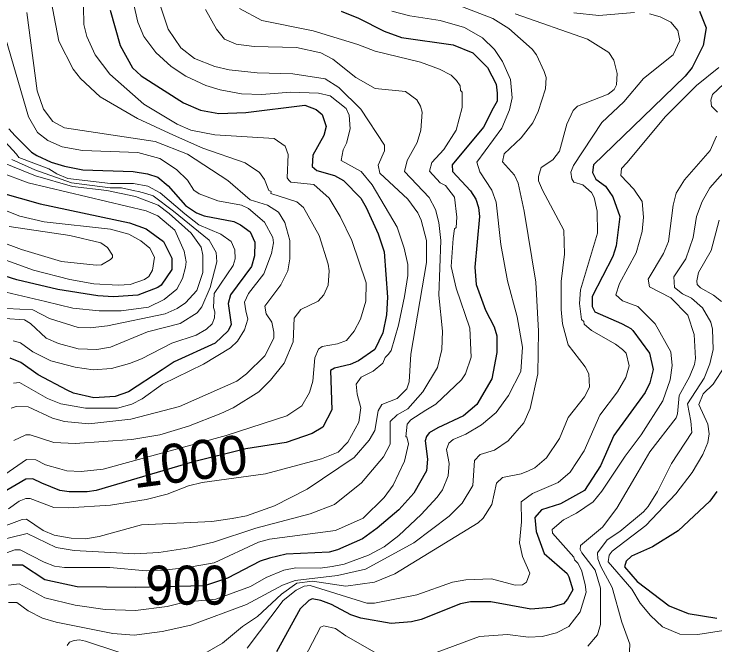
# Model space of a CAD drawing. Extents: x 423 to 448.8, y 7456.3 to 7484.
# Drawn here: x 436.1 to 437.534, y 7472.399 to 7473.69 of the extents above; entities that cross this region are included whole.
import ezdxf
from ezdxf.enums import TextEntityAlignment as Align

# ---------------------------------------------------------------- set-up
doc = ezdxf.new("R2010")
doc.units = 0
doc.header["$LTSCALE"] = 0.032
doc.layers.add('1', color=7, linetype='Continuous', lineweight=25)
doc.layers.add('2', color=7, linetype='Continuous', lineweight=13)
doc.layers.add('61', color=7, linetype='Continuous')

msp = doc.modelspace()

# ---------------------------------------------------------------- linework, layer by layer
at = {"layer": '1'}
for points in [[(436.2966, 7473.6981), (436.3167, 7473.6254), (436.3422, 7473.5797), (436.36, 7473.5635), (436.4466, 7473.5086), (436.4815, 7473.4931), (436.5186, 7473.4862), (436.5743, 7473.4885), (436.6949, 7473.5039), (436.7181, 7473.4947), (436.7305, 7473.4846), (436.7382, 7473.4599), (436.7336, 7473.4413), (436.7112, 7473.4011), (436.7096, 7473.3778), (436.7197, 7473.3701), (436.7553, 7473.3593), (436.7738, 7473.3492), (436.8094, 7473.3129), (436.8202, 7473.2944), (436.845, 7473.2402), (436.8574, 7473.2031), (436.8643, 7473.1103), (436.862, 7473.0747), (436.8543, 7473.0376), (436.838, 7473.0035), (436.8047, 7472.9803), (436.7878, 7472.9726), (436.7552, 7472.9656), (436.7475, 7472.9602), (436.7498, 7472.8798), (436.732, 7472.8442), (436.7096, 7472.8318), (436.6563, 7472.8132), (436.574, 7472.8), (436.464, 7472.7727), (436.268, 7472.715), (436.2494, 7472.7119), (436.2123, 7472.7119), (436.1937, 7472.715), (436.1566, 7472.7297), (436.138, 7472.739), (436.1241, 7472.7382), (436.0762, 7472.7103)], [(436.7692, 7473.6958), (436.8048, 7473.6818), (436.8574, 7473.6548), (436.8929, 7473.6424), (436.9981, 7473.6269), (437.0383, 7473.6107), (437.0685, 7473.5805), (437.0863, 7473.5465), (437.0886, 7473.5279), (437.0883, 7473.5116), (437.0801, 7473.4977), (437.0607, 7473.4583), (436.9965, 7473.3817), (436.9973, 7473.3678), (437.0337, 7473.3284), (437.0445, 7473.3114), (437.0499, 7473.2944), (437.0523, 7473.2758), (437.043, 7473.1721), (437.0453, 7473.1366), (437.0646, 7473.084), (437.0824, 7473.0499), (437.0878, 7473.0314), (437.0878, 7472.9973), (437.0778, 7472.9432), (437.0468, 7472.8906), (437.0198, 7472.8674), (436.9672, 7472.8434), (436.9494, 7472.8326), (436.944, 7472.8256), (436.9409, 7472.8164), (436.9455, 7472.7792), (436.944, 7472.7552), (436.9177, 7472.7096), (436.8875, 7472.6755), (436.8426, 7472.6377), (436.8125, 7472.616), (436.7615, 7472.5936), (436.7444, 7472.5889), (436.6563, 7472.5843), (436.6222, 7472.5766), (436.6037, 7472.5704), (436.5364, 7472.5356), (436.4894, 7472.5194), (436.3492, 7472.5162), (436.2293, 7472.5178), (436.1628, 7472.5317), (436.1171, 7472.5619), (436.0963, 7472.5619)], [(437.5024, 7473.6958), (437.5163, 7473.6617), (437.5102, 7473.6254), (437.4877, 7473.5805), (437.473, 7473.5627), (437.4073, 7473.4993), (437.2858, 7473.3817), (437.2835, 7473.3655), (437.2905, 7473.3523), (437.3098, 7473.3377), (437.3253, 7473.316), (437.3392, 7473.2758), (437.3322, 7473.2155), (437.3253, 7473.1938), (437.2828, 7473.1118), (437.2828, 7473.0917), (437.2881, 7473.0809), (437.3431, 7473.0569), (437.3547, 7473.0507), (437.3622, 7473.0467), (437.3663, 7473.0422), (437.4003, 7472.9958), (437.4073, 7472.9625), (437.4011, 7472.9355), (437.391, 7472.9154), (437.3268, 7472.8272), (437.2998, 7472.7653), (437.2673, 7472.715), (437.2178, 7472.6879), (437.1791, 7472.6755), (437.1652, 7472.6593), (437.1683, 7472.6307), (437.1845, 7472.5859), (437.2317, 7472.5448), (437.2348, 7472.5379), (437.2433, 7472.5116), (437.2325, 7472.4923), (437.224, 7472.483), (437.1977, 7472.4752), (437.1575, 7472.4721), (437.0755, 7472.4868), (437.0337, 7472.4868), (437.0136, 7472.483), (436.9332, 7472.4505), (436.9131, 7472.4459), (436.8713, 7472.4427), (436.8094, 7472.4536), (436.7893, 7472.4605), (436.7491, 7472.4814), (436.7274, 7472.4899), (436.7096, 7472.493), (436.7027, 7472.4899), (436.6856, 7472.4729), (436.6369, 7472.3848)], [(436.0893, 7473.4552), (436.1024, 7473.4405), (436.1357, 7473.4072), (436.1465, 7473.4003), (436.1756, 7473.3866), (436.2029, 7473.3786), (436.2403, 7473.3712), (436.3438, 7473.3678), (436.3732, 7473.3632)], [(436.3732, 7473.3632), (436.394, 7473.3562), (436.4149, 7473.3384), (436.4505, 7473.2982), (436.4729, 7473.2835), (436.4891, 7473.2773), (436.5495, 7473.2657), (436.5634, 7473.2588), (436.5828, 7473.2441), (436.5928, 7473.2232), (436.5921, 7473.1953), (436.5859, 7473.1736), (436.5426, 7473.1157), (436.5379, 7473.0979), (436.5441, 7473.0546), (436.5379, 7473.0414), (436.5116, 7473.0167), (436.4273, 7472.978), (436.4026, 7472.9617), (436.3337, 7472.9169), (436.3067, 7472.9076), (436.2633, 7472.9045), (436.2216, 7472.9138), (436.2084, 7472.92), (436.1489, 7472.9517), (436.114, 7472.9772), (436.0916, 7472.9857)], [(436.0715, 7473.3245), (436.1535, 7473.3013), (436.3361, 7473.2626), (436.3701, 7473.2502), (436.4056, 7473.2247), (436.4227, 7473.1907), (436.4227, 7473.1675), (436.401, 7473.135), (436.394, 7473.1304), (436.3531, 7473.1149), (436.3036, 7473.111), (436.2711, 7473.1133), (436.1891, 7473.1265), (436.1056, 7473.1458), (436.0073, 7473.1768)], [(437.538, 7472.7127), (437.5233, 7472.6933), (437.4591, 7472.6322), (437.4065, 7472.5998), (437.3632, 7472.5804), (437.3523, 7472.5704), (437.3492, 7472.5588), (437.3748, 7472.5286), (437.4405, 7472.4791), (437.4792, 7472.4629), (437.538, 7472.4536)]]:
    msp.add_lwpolyline(points, dxfattribs=at)
at = {"layer": '2'}
for points in [[(436.3399, 7473.7306), (436.3531, 7473.6733), (436.3654, 7473.644), (436.3902, 7473.6114), (436.4211, 7473.5828), (436.4513, 7473.5627), (436.4923, 7473.5441), (436.5217, 7473.5349), (436.565, 7473.5271), (436.6068, 7473.5256), (436.6655, 7473.5302), (436.7228, 7473.5279), (436.7467, 7473.5225), (436.7792, 7473.497), (436.7854, 7473.4831), (436.7877, 7473.4552), (436.78, 7473.4258), (436.773, 7473.4119), (436.7692, 7473.3902), (436.8101, 7473.3678), (436.8326, 7473.3408), (436.8837, 7473.2541), (436.8983, 7473.2108), (436.9053, 7473.1775), (436.9053, 7473.1551), (436.8991, 7473.1118), (436.8867, 7473.053), (436.8712, 7473.0012), (436.8658, 7472.9942), (436.8589, 7472.9873), (436.8543, 7472.9756), (436.8349, 7472.9594), (436.8102, 7472.947), (436.8001, 7472.9324), (436.8016, 7472.9123), (436.8094, 7472.8844), (436.8055, 7472.855), (436.7831, 7472.814), (436.763, 7472.7931), (436.729, 7472.78), (436.6145, 7472.749), (436.4846, 7472.7313), (436.4567, 7472.7243), (436.4134, 7472.7073), (436.3701, 7472.6964), (436.2974, 7472.6848), (436.2108, 7472.6794), (436.1814, 7472.6802), (436.1326, 7472.6988), (436.1241, 7472.6988), (436.1102, 7472.6933), (436.0885, 7472.6771)], [(436.1721, 7473.7352), (436.1914, 7473.6347), (436.2208, 7473.5774), (436.2355, 7473.5581), (436.2757, 7473.5209), (436.3523, 7473.4761), (436.4258, 7473.442), (436.4861, 7473.4158), (436.5727, 7473.3856), (436.6021, 7473.3655), (436.6121, 7473.3516), (436.6214, 7473.3291), (436.6261, 7473.3268), (436.6253, 7473.3229), (436.6787, 7473.3059), (436.6918, 7473.2944), (436.7243, 7473.2371), (436.7429, 7473.1783), (436.7444, 7473.1644), (436.7429, 7473.135), (436.7336, 7473.1157), (436.722, 7473.1025), (436.6864, 7473.0855), (436.6733, 7473.0677), (436.6709, 7473.019), (436.6524, 7472.9757), (436.6245, 7472.9409), (436.6006, 7472.9169), (436.548, 7472.8844), (436.5232, 7472.8728), (436.4567, 7472.8465), (436.3979, 7472.8287), (436.3407, 7472.8194), (436.2247, 7472.8109), (436.1814, 7472.8133), (436.1326, 7472.8287), (436.1241, 7472.8287), (436.0994, 7472.8171)], [(436.9734, 7473.7228), (437.0793, 7473.6811), (437.1126, 7473.6602), (437.1598, 7473.6184), (437.169, 7473.6068), (437.1845, 7473.5728), (437.1884, 7473.5604), (437.1876, 7473.5372), (437.1721, 7473.4908), (437.1613, 7473.4676), (437.1373, 7473.4366), (437.1141, 7473.415), (437.103, 7473.4037), (437.0994, 7473.3879), (437.1242, 7473.3601), (437.1312, 7473.3439), (437.1435, 7473.2866), (437.1675, 7473.1412), (437.1729, 7473.0407), (437.1714, 7472.954), (437.1559, 7472.8829), (437.1427, 7472.8535), (437.1111, 7472.8163), (437.0832, 7472.7977), (437.0538, 7472.7885), (437.0422, 7472.7761), (437.0383, 7472.725), (437.0166, 7472.6887), (436.9904, 7472.6624), (436.9177, 7472.6075), (436.8187, 7472.5541), (436.7615, 7472.541), (436.6748, 7472.5309), (436.6493, 7472.5209), (436.5758, 7472.4814), (436.4614, 7472.4389), (436.4026, 7472.4265), (436.3453, 7472.4188), (436.302, 7472.4219), (436.186, 7472.4451), (436.1582, 7472.4536), (436.1288, 7472.4683), (436.1055, 7472.4853), (436.0885, 7472.4853)], [(436.9331, 7473.2681), (436.9262, 7473.2835), (436.9053, 7473.3114), (436.848, 7473.3647), (436.845, 7473.381), (436.8581, 7473.4104), (436.8581, 7473.4219), (436.8094, 7473.4954), (436.7645, 7473.5395), (436.7367, 7473.5573), (436.6702, 7473.5674), (436.5975, 7473.5697), (436.5402, 7473.5759), (436.5109, 7473.5828), (436.4691, 7473.5991), (436.4412, 7473.6207), (436.4149, 7473.6594), (436.3963, 7473.7167)], [(436.0669, 7472.5812), (436.1017, 7472.5936), (436.1125, 7472.5936), (436.1612, 7472.568), (436.1829, 7472.5603), (436.203, 7472.5572), (436.2958, 7472.5572), (436.3701, 7472.5503), (436.4039, 7472.5519), (436.4505, 7472.5564), (436.509, 7472.5669), (436.5998, 7472.6091), (436.6222, 7472.6152), (436.7576, 7472.633), (436.814, 7472.6585), (436.8574, 7472.7003), (436.8759, 7472.7258), (436.8991, 7472.7746), (436.9069, 7472.8102), (436.9038, 7472.8248), (436.9014, 7472.8248), (436.9045, 7472.8504), (436.9115, 7472.8597), (436.9424, 7472.879), (436.9626, 7472.8913), (437.0151, 7472.9417), (437.0236, 7472.954), (437.0353, 7472.9881), (437.0322, 7473.0468), (437.0043, 7473.1288), (436.9942, 7473.1737), (436.9981, 7473.2309), (437.0012, 7473.2502), (437.0043, 7473.2533), (437.0059, 7473.2742), (437.0012, 7473.3152), (436.9827, 7473.3392), (436.9718, 7473.3446), (436.9502, 7473.3686), (436.9548, 7473.3864), (436.9796, 7473.4127), (437.0043, 7473.4521), (437.0167, 7473.4985), (437.0167, 7473.5302), (437.0136, 7473.5333), (437.0128, 7473.5434), (437.0051, 7473.5542), (436.9943, 7473.565), (436.9703, 7473.5774), (436.9316, 7473.5914), (436.8388, 7473.6138), (436.8032, 7473.6277), (436.712, 7473.6555), (436.6068, 7473.6772), (436.5611, 7473.7012)], [(436.2416, 7473.7058), (436.2424, 7473.6687), (436.2486, 7473.644), (436.2656, 7473.6068), (436.2958, 7473.5673), (436.3654, 7473.5055), (436.4335, 7473.4645), (436.4614, 7473.4521), (436.5109, 7473.4428), (436.6323, 7473.4351), (436.6547, 7473.4196), (436.6609, 7473.4026), (436.6586, 7473.3547), (436.6624, 7473.35), (436.6663, 7473.3462), (436.7135, 7473.3415), (436.7444, 7473.3129), (436.7668, 7473.2758), (436.7908, 7473.2263), (436.8202, 7473.1397), (436.8194, 7473.1025), (436.8086, 7473.0654), (436.7955, 7473.0407), (436.78, 7473.0221), (436.7615, 7473.0151), (436.7305, 7473.0097), (436.7227, 7473.0043), (436.715, 7472.9865), (436.7111, 7472.9386), (436.7042, 7472.9154), (436.6887, 7472.8883), (436.6578, 7472.8674), (436.5339, 7472.8277), (436.2819, 7472.7583), (436.237, 7472.7537), (436.2077, 7472.7552), (436.1937, 7472.7591), (436.1643, 7472.7676), (436.1442, 7472.7777), (436.1256, 7472.7784), (436.0808, 7472.7475)], [(436.4915, 7473.6996), (436.5139, 7473.6594), (436.5302, 7473.6385), (436.5542, 7473.6285), (436.5913, 7473.6238), (436.6779, 7473.6215), (436.7274, 7473.6107), (436.7522, 7473.5975), (436.7993, 7473.5604), (436.8388, 7473.538), (436.9007, 7473.5318), (436.9238, 7473.5148), (436.9316, 7473.5016), (436.9347, 7473.4893), (436.9324, 7473.4521), (436.9246, 7473.4274), (436.9045, 7473.3903), (436.8991, 7473.3678), (436.9494, 7473.3145), (436.9625, 7473.2897), (436.9687, 7473.2634), (436.9734, 7473.2263), (436.9687, 7473.1149), (436.9765, 7473.0407), (436.9749, 7473.0035), (436.9664, 7472.9664), (436.9362, 7472.9169), (436.9053, 7472.8821), (436.8837, 7472.8697), (436.8697, 7472.8558), (436.8697, 7472.8457), (436.8697, 7472.8094), (436.8558, 7472.7839), (436.8109, 7472.7305), (436.7553, 7472.6864), (436.7058, 7472.667), (436.5944, 7472.6376), (436.5078, 7472.6091), (436.4583, 7472.5974), (436.3964, 7472.5881)], [(436.8728, 7473.6957), (436.91, 7473.6865), (436.9718, 7473.6772), (437.0213, 7473.6625), (437.0584, 7473.6416), (437.0832, 7473.6177), (437.0994, 7473.5929), (437.1157, 7473.5558), (437.1188, 7473.5187), (437.1133, 7473.4939), (437.0979, 7473.4568), (437.0468, 7473.3872), (437.053, 7473.3671), (437.0778, 7473.3299), (437.0863, 7473.3052)], [(436.1257, 7473.6935), (436.1473, 7473.5326), (436.1604, 7473.4954), (436.179, 7473.4699), (436.203, 7473.4575), (436.3886, 7473.4289), (436.4544, 7473.4034), (436.5371, 7473.3492), (436.5828, 7473.3098), (436.6183, 7473.299), (436.6408, 7473.2843), (436.6539, 7473.2634), (436.664, 7473.2263), (436.664, 7473.1892), (436.6601, 7473.1644), (436.6454, 7473.1358), (436.6129, 7473.0925), (436.616, 7473.0762), (436.6276, 7473.0592), (436.6315, 7473.0391), (436.6315, 7473.0267), (436.6129, 7472.9904), (436.5758, 7472.954), (436.5557, 7472.9385), (436.4381, 7472.8867), (436.3391, 7472.8612), (436.2525, 7472.8511), (436.203, 7472.8558), (436.1783, 7472.8628), (436.1288, 7472.886), (436.104, 7472.8867), (436.0939, 7472.8836)], [(437.125, 7473.6904), (437.2734, 7473.6385), (437.3168, 7473.6114), (437.3268, 7473.596), (437.3338, 7473.5682), (437.3323, 7473.545), (437.3276, 7473.5357), (437.3153, 7473.5263), (437.2526, 7473.5016), (437.2441, 7473.4924), (437.2309, 7473.4645), (437.2162, 7473.4096), (437.2023, 7473.3918), (437.1783, 7473.3763), (437.1729, 7473.3578), (437.1729, 7473.3484), (437.1814, 7473.3299), (437.2247, 7473.2479), (437.2263, 7473.1984), (437.2193, 7473.1428), (437.2193, 7473.0855), (437.2224, 7473.0561), (437.234, 7473.0128), (437.2688, 7472.9679), (437.2758, 7472.954), (437.2773, 7472.9262), (437.2673, 7472.9068), (437.234, 7472.8643), (437.2162, 7472.821), (437.1891, 7472.7815), (437.1652, 7472.7614), (437.1528, 7472.7552), (437.1374, 7472.749), (437.0994, 7472.7413), (437.0871, 7472.7297), (437.0778, 7472.6864), (437.06, 7472.6585), (437.0492, 7472.6485), (436.879, 7472.5441), (436.8373, 7472.5271), (436.7785, 7472.5193), (436.7102, 7472.5295), (436.6786, 7472.525), (436.6471, 7472.5025), (436.5982, 7472.4567), (436.5673, 7472.4366), (436.5263, 7472.4025), (436.4815, 7472.3762)], [(437.2456, 7473.6926), (437.2967, 7473.6873), (437.3694, 7473.6934)], [(437.4003, 7473.6904), (437.422, 7473.6842), (437.4436, 7473.6733), (437.4583, 7473.6563), (437.4622, 7473.6362), (437.4483, 7473.6068), (437.3879, 7473.5581), (437.3477, 7473.5101), (437.3028, 7473.4684)], [(436.0777, 7473.6579), (436.1295, 7473.48), (436.1481, 7473.4475), (436.1689, 7473.4312), (436.1984, 7473.4181), (436.2401, 7473.4111), (436.3531, 7473.4065), (436.3979, 7473.3941), (436.4319, 7473.3717), (436.4544, 7473.35), (436.4675, 7473.3299), (436.4783, 7473.3222), (436.517, 7473.3075)], [(436.9656, 7472.384), (437.0523, 7472.4157), (437.1095, 7472.4203), (437.1528, 7472.4149), (437.1807, 7472.4157), (437.2101, 7472.4234), (437.2348, 7472.4366), (437.258, 7472.4667), (437.2704, 7472.507), (437.2688, 7472.5224), (437.2611, 7472.5518), (437.2533, 7472.5658), (437.2464, 7472.5727), (437.2456, 7472.5781), (437.2015, 7472.6276), (437.2008, 7472.6353), (437.224, 7472.6547), (437.251, 7472.6686), (437.2851, 7472.6918), (437.3029, 7472.7134), (437.35, 7472.7854), (437.3833, 7472.8287), (437.4274, 7472.8983), (437.4421, 7472.9417), (437.4467, 7472.971), (437.4436, 7472.9989), (437.4119, 7473.0561), (437.3763, 7473.0917), (437.3446, 7473.1033), (437.3315, 7473.1157), (437.3384, 7473.1389), (437.3725, 7473.2015), (437.3849, 7473.2448), (437.388, 7473.2742), (437.3849, 7473.3067), (437.3678, 7473.3315), (437.3415, 7473.3593), (437.3426, 7473.3739), (437.3539, 7473.3856), (437.4328, 7473.4807), (437.4962, 7473.5441), (437.5418, 7473.5805)], [(437.5852, 7473.5782), (437.5287, 7473.5256), (437.5256, 7473.514), (437.5271, 7473.5016), (437.5395, 7473.4893)], [(437.3028, 7473.4684), (437.2448, 7473.3802), (437.239, 7473.3665), (437.241, 7473.3531), (437.2456, 7473.3461), (437.2634, 7473.3408), (437.2812, 7473.3245), (437.2866, 7473.3145), (437.2928, 7473.2866), (437.2936, 7473.2418), (437.2588, 7473.1257), (437.2572, 7473.0979), (437.2611, 7473.0646), (437.2657, 7473.0608), (437.2665, 7473.0553), (437.2812, 7473.0422), (437.3307, 7473.0144), (437.3446, 7473.0035), (437.3523, 7472.9957), (437.3586, 7472.9702), (437.3516, 7472.9463), (437.3346, 7472.9169), (437.2982, 7472.8689), (437.2665, 7472.7962), (437.2379, 7472.7521), (437.2131, 7472.7313), (437.1605, 7472.7088), (437.1373, 7472.6918), (437.1381, 7472.6508), (437.1343, 7472.6075), (437.1404, 7472.5797), (437.1551, 7472.5456), (437.1481, 7472.527), (437.1404, 7472.5216), (437.125, 7472.5208), (437.077, 7472.534), (437.0244, 7472.5317), (436.9973, 7472.5271), (436.9239, 7472.5015), (436.8373, 7472.4845), (436.8218, 7472.4845), (436.7058, 7472.5201), (436.6933, 7472.5193), (436.6771, 7472.5108), (436.6508, 7472.49), (436.5766, 7472.3924)], [(436.0653, 7473.4459), (436.1048, 7473.4034), (436.1094, 7473.3963), (436.1707, 7473.3731), (436.1872, 7473.363), (436.2096, 7473.3533), (436.2974, 7473.3435), (436.3439, 7473.3435), (436.3737, 7473.338), (436.3986, 7473.3242), (436.4492, 7473.2814), (436.4777, 7473.2589), (436.5232, 7473.2394), (436.5441, 7473.2247), (436.5518, 7473.2077), (436.5526, 7473.1891), (436.5479, 7473.1752), (436.5093, 7473.118), (436.5078, 7473.0894), (436.5108, 7473.0809), (436.51, 7473.0685), (436.5054, 7473.0561), (436.4938, 7473.0453), (436.4722, 7473.0329), (436.4227, 7473.0166), (436.3608, 7472.9842), (436.3361, 7472.9749), (436.2989, 7472.9648), (436.2618, 7472.9618), (436.2247, 7472.9671), (436.1752, 7472.9803), (436.138, 7472.9989), (436.1133, 7473.0174), (436.0978, 7473.0213)], [(437.5372, 7473.4398), (437.524, 7473.4111), (437.4715, 7473.3508), (437.4545, 7473.3237), (437.4483, 7473.299), (437.439, 7473.2247), (437.4289, 7473.2), (437.3972, 7473.1473), (437.4003, 7473.1319), (437.4436, 7473.1095), (437.4784, 7473.0739), (437.4916, 7473.0345), (437.4939, 7472.985)], [(436.0709, 7473.3883), (436.144, 7473.3587), (436.2195, 7473.3372), (436.2896, 7473.3291), (436.3484, 7473.3168), (436.3948, 7473.299), (436.4173, 7473.282), (436.4621, 7473.2418), (436.483, 7473.2131), (436.4861, 7473.1969), (436.4861, 7473.1613), (436.4737, 7473.1242), (436.4505, 7473.0987), (436.4335, 7473.0871), (436.4088, 7473.0762), (436.2912, 7473.0522), (436.2556, 7473.0476), (436.2309, 7473.0484), (436.1721, 7473.0669), (436.138, 7473.0847), (436.0313, 7473.0901)], [(436.0956, 7473.3925), (436.1424, 7473.3709), (436.2177, 7473.3448), (436.2964, 7473.3343), (436.3195, 7473.3343), (436.3469, 7473.3283), (436.3542, 7473.3271), (436.3694, 7473.3228), (436.3846, 7473.3179), (436.4259, 7473.2864), (436.4992, 7473.227), (436.5132, 7473.2023), (436.5147, 7473.183), (436.5008, 7473.1304), (436.4838, 7473.0909), (436.4745, 7473.0785), (436.4397, 7473.0569), (436.3732, 7473.0398), (436.2974, 7473.0082), (436.2695, 7473.0035), (436.2309, 7473.0051), (436.1906, 7473.0159), (436.1658, 7473.0267), (436.1334, 7473.0569), (436.121, 7473.0639), (436.0808, 7473.0669)], [(436.07, 7473.3662), (436.1288, 7473.3446), (436.3701, 7473.2874), (436.394, 7473.2773), (436.4288, 7473.2479), (436.4482, 7473.2046), (436.452, 7473.183), (436.4505, 7473.1721), (436.4443, 7473.1489), (436.4327, 7473.1273), (436.4072, 7473.1056), (436.3747, 7473.0902), (436.319, 7473.0824), (436.2742, 7473.0824), (436.22, 7473.0878), (436.1643, 7473.1017), (436.0127, 7473.1373)], [(437.5604, 7473.3763), (437.5233, 7473.3346), (437.5078, 7473.3067), (437.4962, 7473.2758), (437.4892, 7473.2325), (437.4745, 7473.1892), (437.4498, 7473.152), (437.4514, 7473.1304), (437.4676, 7473.1172), (437.4862, 7473.1087), (437.5086, 7473.0886), (437.5256, 7473.0592), (437.5287, 7473.0453), (437.5303, 7473.0035), (437.5233, 7472.9741), (437.5117, 7472.9447), (437.4777, 7472.8921), (437.4846, 7472.8566), (437.487, 7472.8334), (437.4452, 7472.7699), (437.4165, 7472.7127), (437.3972, 7472.6818), (437.388, 7472.6709), (437.3392, 7472.6307), (437.3137, 7472.6137), (437.2936, 7472.5874), (437.2943, 7472.575), (437.3005, 7472.5596), (437.3237, 7472.5162), (437.3438, 7472.4451), (437.3601, 7472.4002), (437.3586, 7472.3708)], [(436.0127, 7473.2116), (436.1396, 7473.1659), (436.2138, 7473.1466), (436.2633, 7473.1381), (436.3128, 7473.135), (436.3376, 7473.1366), (436.3669, 7473.1466), (436.3755, 7473.1528), (436.3832, 7473.166), (436.3871, 7473.1923), (436.3778, 7473.2108), (436.3593, 7473.2262), (436.3345, 7473.2394), (436.2974, 7473.2495), (436.1612, 7473.265), (436.1117, 7473.2765), (436.0127, 7473.3152)], [(437.0863, 7473.3052), (437.0956, 7473.2186), (437.1095, 7473.1443), (437.1296, 7473.07), (437.1404, 7473.0082), (437.1365, 7472.9587), (437.1118, 7472.9092), (437.0863, 7472.8743), (437.0561, 7472.8496), (437.0244, 7472.8303), (436.9981, 7472.8194), (436.9896, 7472.8117), (436.985, 7472.7985), (436.9904, 7472.7699), (436.988, 7472.7452), (436.9765, 7472.7165), (436.9656, 7472.7011), (436.9332, 7472.6655), (436.8875, 7472.623), (436.8574, 7472.5997), (436.8249, 7472.5828), (436.7754, 7472.5642), (436.7506, 7472.5596), (436.7259, 7472.5557), (436.6764, 7472.5564), (436.6516, 7472.5518), (436.616, 7472.5371), (436.5836, 7472.5185), (436.5128, 7472.4924), (436.4483, 7472.4864), (436.413, 7472.4774), (436.3484, 7472.469), (436.2865, 7472.4714), (436.2247, 7472.4799), (436.1628, 7472.4953), (436.1102, 7472.524), (436.0885, 7472.5209)], [(436.517, 7473.3075), (436.565, 7473.299), (436.5797, 7473.292), (436.6121, 7473.2642), (436.6292, 7473.2325), (436.6307, 7473.2216), (436.6268, 7473.2), (436.6106, 7473.1582), (436.5797, 7473.118), (436.5712, 7473.1002), (436.5743, 7473.0824), (436.5781, 7473.0654), (436.5712, 7473.0437), (436.5573, 7473.0205), (436.5425, 7473.0066), (436.4876, 7472.9733), (436.4033, 7472.9324), (436.3623, 7472.9022), (436.3407, 7472.8913), (436.3113, 7472.8836), (436.2463, 7472.8836), (436.1953, 7472.8921), (436.1682, 7472.9029), (436.111, 7472.9362), (436.0986, 7472.9347)], [(436.0592, 7472.6346), (436.1164, 7472.6554), (436.1256, 7472.6562), (436.1597, 7472.633), (436.1821, 7472.6237), (436.2169, 7472.6175), (436.2463, 7472.616), (436.2742, 7472.6206), (436.3608, 7472.6446), (436.5047, 7472.6516), (436.5464, 7472.6578), (436.5758, 7472.6632), (436.6331, 7472.6833), (436.6996, 7472.7173), (436.7955, 7472.7823), (436.8264, 7472.8179), (436.838, 7472.838), (436.845, 7472.8782), (436.8527, 7472.8906), (436.8837, 7472.9029), (436.9038, 7472.9231), (436.9084, 7472.937), (436.9115, 7472.9942), (436.944, 7473.1814), (436.944, 7473.2263), (436.9331, 7473.2681)], [(437.5426, 7473.2681), (437.5264, 7473.2062), (437.5001, 7473.1613), (437.497, 7473.1443), (437.4978, 7473.1365), (437.5047, 7473.1296), (437.531, 7473.1149), (437.5473, 7473.1017)], [(436.0901, 7473.2549), (436.2138, 7473.2371), (436.2773, 7473.2216), (436.2911, 7473.2124), (436.3012, 7473.1969), (436.3012, 7473.1915), (436.2973, 7473.1876), (436.2788, 7473.1767), (436.268, 7473.176), (436.1968, 7473.1837), (436.1148, 7473.2085), (435.988, 7473.2549)], [(437.4939, 7472.985), (437.4923, 7472.9726), (437.4823, 7472.9478), (437.4607, 7472.9092), (437.4576, 7472.872), (437.4544, 7472.8635), (437.4011, 7472.7939), (437.3771, 7472.7529), (437.333, 7472.6787), (437.3036, 7472.64), (437.2588, 7472.6021), (437.258, 7472.5943), (437.2619, 7472.5874), (437.2889, 7472.5518), (437.2998, 7472.5147), (437.2998, 7472.4405), (437.2936, 7472.4195), (437.2742, 7472.3963)], [(437.5542, 7472.9695), (437.5303, 7472.9323), (437.5101, 7472.913), (437.5009, 7472.8906), (437.5194, 7472.8504), (437.5225, 7472.831), (437.5194, 7472.8133), (437.5094, 7472.7885), (437.4877, 7472.7514), (437.4537, 7472.708), (437.3926, 7472.6431), (437.3237, 7472.5905), (437.3176, 7472.5828), (437.3152, 7472.5688), (437.3639, 7472.5132), (437.381, 7472.4845), (437.4019, 7472.459), (437.4266, 7472.4358), (437.4622, 7472.4211), (437.4993, 7472.4203), (437.5736, 7472.4319)], [(436.3964, 7472.5881), (436.3469, 7472.5851), (436.2231, 7472.592), (436.186, 7472.5982), (436.1264, 7472.6268), (436.0561, 7472.6098)], [(436.6941, 7472.3724), (436.7266, 7472.435), (436.7336, 7472.4381), (436.7576, 7472.4327), (436.7785, 7472.4172), (436.8373, 7472.384)], [(436.3825, 7472.3616), (436.2463, 7472.4064), (436.234, 7472.4095), (436.2231, 7472.408), (436.213, 7472.4041), (436.2084, 7472.3979)]]:
    msp.add_lwpolyline(points, dxfattribs=at)

# ---------------------------------------------------------------- texts
at = {"layer": '61'}
msp.add_text('1000', height=0.08, rotation=7.595, dxfattribs=at).set_placement((436.4637, 7472.735), align=Align.CENTER)
at = {"layer": '61', "width": 0.95}
msp.add_text('900', height=0.08, dxfattribs=at).set_placement((436.4534, 7472.4811), align=Align.CENTER)

doc.saveas('drawing.dxf')
